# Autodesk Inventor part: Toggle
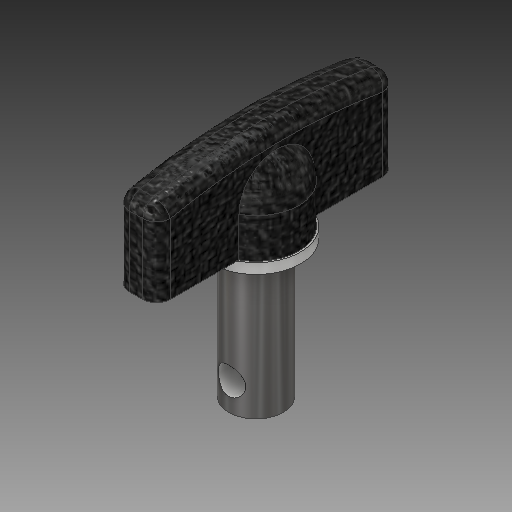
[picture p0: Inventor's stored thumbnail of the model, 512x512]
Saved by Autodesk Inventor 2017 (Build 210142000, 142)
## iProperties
Created: 2020-03
Part Number: Toggle
Material: Generic
Document SubType Name: Modeling
Designer: user
Density: 1 g/cm^3
Appearance: Default
Mass: 4.27175 g
Surface Area: 21.4512 cm^2
Volume: 4.27175 cm^3
Author: user
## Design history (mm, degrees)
sketch "Sketch1"
  geometry: C1 r 4 at (0, 0); 1 further point
  constraints: 1 centre point, 1 coincident
  dimensions: "d0" = 8 diameter of C1
extrude "Extrusion1" new body sketch "Sketch1" distance "d1" = 20; taper "d2" = 0 deg
sketch "Sketch3"
  geometry: C1 r 6.5 at (0, 0); 1 further point
  constraints: 1 centre point, 1 coincident
  dimensions: "d7" = 13 diameter of C1
extrude "Extrusion3" join sketch "Sketch3" distance "d8" = 1.5; taper "d9" = 0 deg
sketch "Sketch4"
  geometry: L1 (21.5, -6.5)-(21.5, 6.5) reference; L2 (21.5, 6.25)-(27.25, 6.25); L3 (33.5, 0)-(33.5, 0); L4 (33.5, 0)-(21.5, 0); L5 (21.5, 6.25)-(21.5, 0); A1 r 6.25 centre (27.25, 0) between (33.5, 0) and (27.25, 6.25); 1 further point
  constraints: 8 end point, 2 point on circle, 2 tangent, 1 centre point, 1 collinear, 1 horizontal, 1 midpoint, 1 perpendicular, 1 point on line
  dimensions: "d10" = 6.25 radius of A1; "d11" = 12 distance from line of L1 L3.end
revolve "Revolution1" sketch "Sketch4" stored, may be unused: angle "d12" = 90 deg
sketch "Sketch5"
  geometry: L1 (21.5, 17.5)-(21.5, -17.5); L2 (21.5, -17.5)-(33.863, -17.5); L3 (33.317, 17.5)-(21.5, 17.5); L4 (21.5, -6.5)-(21.5, 6.5) reference; L5 (0, 0)-(-2.516, 0); A1 r 81.56 centre (-46.06, -1.242) between (33.863, -17.5) and (33.317, 17.5)
  constraints: 8 end point, 2 point on circle, 1 centre point, 1 collinear, 1 horizontal, 1 perpendicular, 1 vertical, 1 other
  dimensions: "d13" = 35 distance between parallel lines of L2 L3; "d15" = 14 distance edge to line of A1 L1
extrude "Extrusion4" join sketch "Sketch5" stored distance "d16" = 6; taper "d17" = 0 deg
fillet "Fillet1" dims "d18" = 2
sketch "Sketch6"
  geometry: L1 (-4, 0)-(4, 0) reference; C1 r 2 at (0, 4); 1 further point
  constraints: 1 centre point
  dimensions: "d19" = 4 diameter of C1; "d20" = 4 distance from line of C1.centre L1
extrude "Extrusion5" cut sketch "Sketch6" stored distance "d21" = 6; taper "d22" = 0 deg
body "Solid1"
